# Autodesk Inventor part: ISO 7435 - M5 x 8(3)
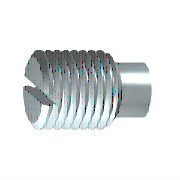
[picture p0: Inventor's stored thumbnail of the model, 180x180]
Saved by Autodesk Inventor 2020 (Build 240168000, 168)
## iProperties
Created: 2019-01
Part Number: ISO 7435 - M5 x 8(3)
Material: Acier inoxydable 440C
Description: Vis sans tête fendues entièrement filetée à téton long
Document SubType Name: Modeling
Standard: ISO 7435
Designer: %USERNAME%
Standard Revision: First edition 1983-09-01
Standards Organization: ISO
Language: fr-FR
Size Designation: M5 x 8
Categories: <MemberInstance><Categories><Category DisplayName="Visserie" InternalName="e4da775c-781d-43d5-af7c-5136215cf5a6" Mnemonic="FSTN"><Category DisplayName="Vis" Int
Density: 7.75 g/cm^3
Appearance: Semi-poli
IsCustomPart: 0
Author: %USERNAME%
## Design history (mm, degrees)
sketch "Esquisse1"
  geometry: L1 (0, 0)-(8, 0); L2 (8, 0)-(8, 2.5); L3 (8, 2.5)-(2.75, 2.5); L4 (0, -0.5)-(0, 3) reference; L5 (0, 1.75)-(0, 0); L6 (0, 1.75)-(2.75, 1.75); L7 (2.75, 1.75)-(2.75, 2.5)
  constraints: 13 end point, 4 perpendicular, 2 parallel, 1 collinear, 1 point on line
  dimensions: "d1" = 8 distance from line of L2 L5.start (= NLG); "d2" = 3.5 diameter of L5.start L1 (= SPD); "d13" = 5 diameter of L3 L1 (= NND); "d14" = 2.75 distance of L5.start L6.end (= ZLG)
revolve "Corps" sketch "Esquisse1" stored, may be unused: angle "d6" = 90 deg
sketch "Esquisse2"
  geometry: L1 (8, 2.009)-(8, -2.009) reference; L2 (6.464, 0)-(8.256, 0) reference; L3 (8, 0.4)-(6.72, 0.4); L4 (6.72, 0.4)-(6.72, 0); L5 (6.72, -0.4)-(6.72, 0); L6 (6.72, -0.4)-(8, -0.4)
  constraints: 8 end point, 3 point on line, 2 perpendicular, 1 parallel, 1 symmetric about line, 1 other
  dimensions: "d8" = 0.4 distance between parallel lines of L2 L3 (= 0.5 x SBR); "d9" = 1.28 distance between parallel lines of L1 L4 (= STI)
extrude "Rainure" cut sketch "Esquisse2" stored distance "d10" = 5 (= NND); taper "d11" = 0 deg
workaxis "Work Axis1"
workplane "Work Plane1"
body "Solid1"
chamfer "Chanfrein1" distance "d3" = 0.49076 (= -0.5 x GD1 + 0.5 x NND); stored, may be unused: angle "d4" = 60 deg (= FAWI), second distance "d37" = 0.49076 (= -0.5 x GD1 + 0.5 x NND)
feature "Filetage" dims "d5" = 5.25 (= NLG - ZLG), "d7" = 0
chamfer "Chanfrein2" distance "d15" = 0.75 (= -0.5 x SPD + 0.5 x NND); stored, may be unused: angle "d16" = 60 deg (= FAWI), second distance "d38" = 0.75 (= -0.5 x SPD + 0.5 x NND)
other parameters: "NND" = 5 [user parameter; used in 6 equation terms], "NLG" = 8 [user parameter; used in 2 equation terms], "FAWI" = 60 deg [user parameter; used in 2 equation terms], "GD1" = 4.01848 (= THREADDIA - 1.2269 x PTC) [user parameter; used in 2 equation terms], "d0" = 0, "FAWI1" = 45 deg [user parameter], "SPD" = 3.5 [user parameter; used in 3 equation terms], "SBR" = 0.8 [user parameter; used in 1 equation term], "STI" = 1.28 [user parameter; used in 1 equation term], "ZLG" = 2.75 [user parameter; used in 2 equation terms], "d17" = 0, "d39" = 90 deg, "d40" = 0, "GUL" = 0.49076 (= 0.61345 x PTC) [user parameter], "TPU" = 12.5 (computed from PTC) [user parameter], "THREADDIA" = 5 [user parameter; used in 1 equation term], "TOA" = 30 deg [user parameter], "PTC" = 0.8 [user parameter; used in 4 equation terms], "GAL" = 0.49076 (= 0.61345 x PTC) [user parameter]
